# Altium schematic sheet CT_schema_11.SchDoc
size 147 x 119 mm
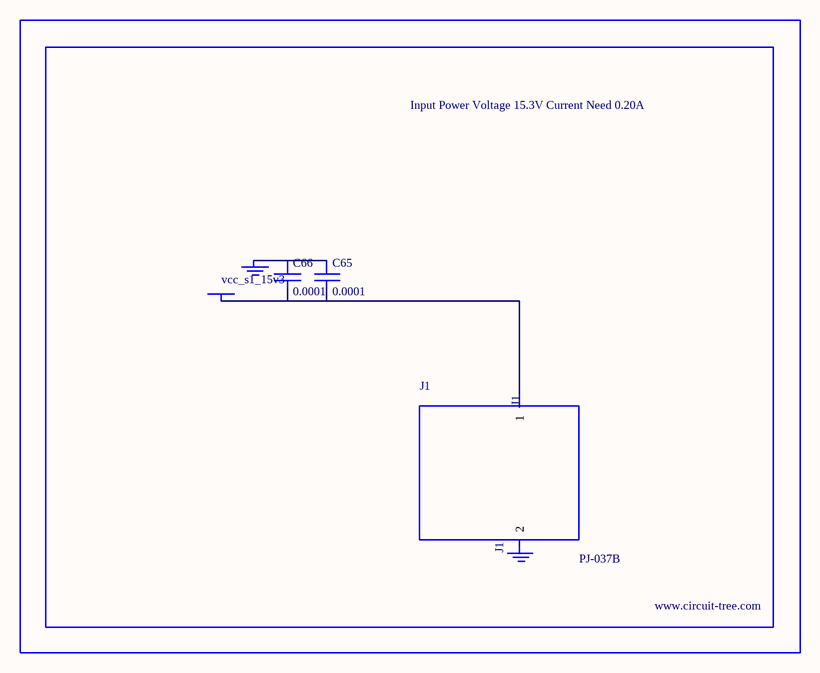
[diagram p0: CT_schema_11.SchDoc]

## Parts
BORDER10  (no value)
C65  0.0001  [EXV-9H]
C66  0.0001  [EXV-9H]
GND_INSTANCE_10_0  (no value)
GND_INSTANCE_10_1  (no value)
J1  PJ-037B  [PJ-037B_PACKAGE]
POWER_INSTANCE_10_0  vcc_s1_15v3

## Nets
NetC65_1: C65.1 C66.1 GND_INSTANCE_10_0.0(GND)
NetC65_2: C65.2 C66.2 J1.1 POWER_INSTANCE_10_0.0(PWR)

Not connected (* = marked no-connect by the designer): GND_INSTANCE_10_1 0(GND); J1 2

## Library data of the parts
BORDER10 = BORDER_PAGE10
C65 C66 = EDK107M035A9HAA
GND_INSTANCE_10_0 GND_INSTANCE_10_1 = GND
POWER_INSTANCE_10_0 = PWR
